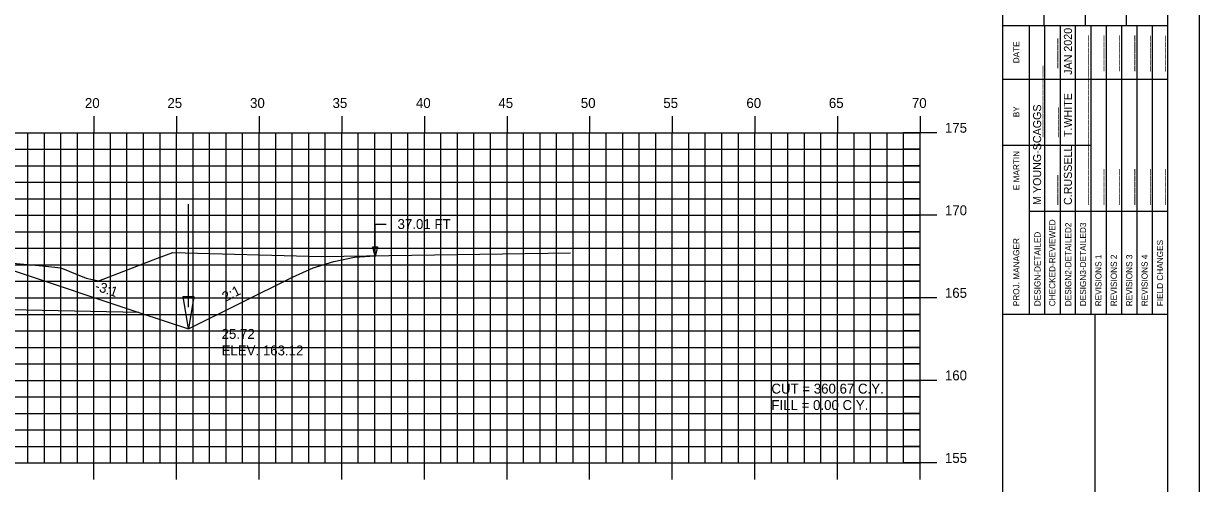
# Model space of a CAD drawing. Extents: x 1141646 to 1141816, y 608981 to 609091.
# Drawn here: x 1141744.8 to 1141815.9, y 609019.1 to 609047 of the extents above; entities that cross this region are included whole.
import ezdxf

# ---------------------------------------------------------------- set-up
doc = ezdxf.new("R2010")
doc.units = 0
for name, color, linetype in [('ANNOTATION', 7, 'Continuous'), ('BORDER', 7, 'Continuous'), ('D_Drainage_Ditch_Line', 7, 'Continuous'), ('D_Roadway_SlopeLines', 7, 'Continuous'), ('D_Roadway_SubGrade', 7, 'Continuous'), ('D_Text_Standard', 7, 'Continuous'), ('H_V ANNOTATION', 7, 'Continuous'), ('MAJOR', 7, 'Continuous'), ('MINOR', 7, 'Continuous'), ('PLOT BOUNDARY', 7, 'Continuous'), ('S_Roadway_Centerline', 7, 'Continuous')]:
    doc.layers.add(name, color=color, linetype=linetype)

msp = doc.modelspace()

# ---------------------------------------------------------------- linework, layer by layer
msp.add_lwpolyline([(1141690.206, 609033.804), (1141691.456, 609033.702), (1141692.706, 609033.45), (1141693.956, 609033.049), (1141695.206, 609032.498), (1141703.303, 609028.45), (1141706.303, 609029.45), (1141714.026, 609032.025), (1141714.027, 609032.025), (1141718.027, 609032.185), (1141729.027, 609032.405), (1141740.027, 609032.185), (1141744.027, 609032.025), (1141751.751, 609029.45), (1141754.751, 609028.45), (1141761.041, 609031.596), (1141762.291, 609032.145), (1141763.541, 609032.543), (1141764.791, 609032.789), (1141766.041, 609032.884)])
at = {"layer": 'BORDER'}
for p, q in [((1141804.027, 608984.335), (1141804.027, 609089.335)), ((1141806.527, 609046.838), (1141806.527, 609055.485)), ((1141809.027, 609046.838), (1141809.027, 609055.485)), ((1141811.527, 609046.838), (1141811.527, 609055.485)), ((1141804.027, 609046.838), (1141814.027, 609046.838)), ((1141804.027, 609029.338), (1141814.027, 609029.338)), ((1141809.618, 608994.338), (1141809.618, 609029.338))]:
    msp.add_line(p, q, dxfattribs=at)
msp.add_lwpolyline([(1141654.027, 608984.335), (1141814.027, 608984.335), (1141814.027, 609089.335), (1141654.027, 609089.335)], close=True, dxfattribs=at)
for points in [[(1141805.642, 609043.588), (1141805.642, 609046.838)], [(1141806.575, 609029.341), (1141806.575, 609046.838)], [(1141807.507, 609046.838), (1141807.507, 609029.341)], [(1141808.438, 609029.341), (1141808.438, 609046.838)], [(1141809.37, 609029.341), (1141809.37, 609046.838)], [(1141810.302, 609029.341), (1141810.302, 609046.838)], [(1141811.233, 609029.341), (1141811.233, 609046.838)], [(1141812.165, 609029.341), (1141812.165, 609046.838)], [(1141813.097, 609029.341), (1141813.097, 609046.838)], [(1141805.643, 609029.341), (1141805.643, 609046.132)], [(1141804.027, 609043.588), (1141814.027, 609043.588)], [(1141804.027, 609039.588), (1141805.643, 609039.588)], [(1141805.642, 609039.588), (1141809.369, 609039.588)], [(1141805.642, 609035.588), (1141814.027, 609035.588)]]:
    msp.add_lwpolyline(points, dxfattribs=at)
at = {"layer": 'D_Drainage_Ditch_Line'}
msp.add_line((1141754.751, 609029.763), (1141754.751, 609036.006), dxfattribs=at)
msp.add_lwpolyline([(1141754.423, 609030.419), (1141755.079, 609030.419), (1141754.751, 609028.45)], close=True, dxfattribs=at)
at = {"layer": 'D_Roadway_SlopeLines'}
for points in [[(1141754.751, 609028.45), (1141761.041, 609031.596), (1141762.291, 609032.145), (1141763.541, 609032.543), (1141764.791, 609032.789), (1141766.041, 609032.884)], [(1141751.751, 609029.45), (1141754.751, 609028.45)]]:
    msp.add_lwpolyline(points, dxfattribs=at)
at = {"layer": 'D_Roadway_SubGrade'}
msp.add_lwpolyline([(1141740.027, 609031.768), (1141740.027, 609031.935), (1141744.027, 609031.775), (1141744.027, 609032.025), (1141744.027, 609032.025), (1141751.751, 609029.45), (1141740.027, 609029.685)], close=True, dxfattribs=at)
at = {"layer": 'D_Text_Standard'}
msp.add_lwpolyline([(1141766.041, 609032.846), (1141766.042, 609034.804), (1141766.722, 609034.804)], dxfattribs=at)
msp.add_lwpolyline([(1141766.041, 609032.846), (1141765.896, 609033.428), (1141766.187, 609033.428)], close=True, dxfattribs=at)
at = {"layer": 'MAJOR'}
for p, q in [((1141749.027, 609041.337), (1141749.027, 609040.335)), ((1141754.027, 609041.337), (1141754.027, 609040.335)), ((1141759.027, 609041.337), (1141759.027, 609040.335)), ((1141764.027, 609041.337), (1141764.027, 609040.335)), ((1141769.027, 609041.337), (1141769.027, 609040.335)), ((1141774.027, 609041.337), (1141774.027, 609040.335)), ((1141779.027, 609041.337), (1141779.027, 609040.335)), ((1141784.027, 609041.337), (1141784.027, 609040.335)), ((1141789.027, 609041.337), (1141789.027, 609040.335)), ((1141794.027, 609041.337), (1141794.027, 609040.335)), ((1141799.027, 609041.337), (1141799.027, 609040.335)), ((1141659.027, 609040.335), (1141799.027, 609040.335)), ((1141659.027, 609040.335), (1141799.027, 609040.335)), ((1141749.027, 609020.335), (1141749.027, 609040.335)), ((1141754.027, 609020.335), (1141754.027, 609040.335)), ((1141759.027, 609020.335), (1141759.027, 609040.335)), ((1141764.027, 609020.335), (1141764.027, 609040.335)), ((1141769.027, 609020.335), (1141769.027, 609040.335)), ((1141774.027, 609020.335), (1141774.027, 609040.335)), ((1141779.027, 609020.335), (1141779.027, 609040.335)), ((1141784.027, 609020.335), (1141784.027, 609040.335)), ((1141789.027, 609020.335), (1141789.027, 609040.335)), ((1141794.027, 609020.335), (1141794.027, 609040.335)), ((1141800.029, 609040.335), (1141798.025, 609040.335)), ((1141799.027, 609020.335), (1141799.027, 609040.335)), ((1141799.027, 609020.335), (1141799.027, 609040.335)), ((1141659.027, 609035.335), (1141799.027, 609035.335)), ((1141800.029, 609035.335), (1141798.025, 609035.335)), ((1141659.027, 609030.335), (1141799.027, 609030.335)), ((1141800.029, 609030.335), (1141798.025, 609030.335)), ((1141659.027, 609025.335), (1141799.027, 609025.335)), ((1141800.029, 609025.335), (1141798.025, 609025.335)), ((1141659.027, 609020.335), (1141799.027, 609020.335)), ((1141659.027, 609020.335), (1141799.027, 609020.335)), ((1141749.027, 609019.333), (1141749.027, 609020.335)), ((1141754.027, 609019.333), (1141754.027, 609020.335)), ((1141759.027, 609019.333), (1141759.027, 609020.335)), ((1141764.027, 609019.333), (1141764.027, 609020.335)), ((1141769.027, 609019.333), (1141769.027, 609020.335)), ((1141774.027, 609019.333), (1141774.027, 609020.335)), ((1141779.027, 609019.333), (1141779.027, 609020.335)), ((1141784.027, 609019.333), (1141784.027, 609020.335)), ((1141789.027, 609019.333), (1141789.027, 609020.335)), ((1141794.027, 609019.333), (1141794.027, 609020.335)), ((1141800.029, 609020.335), (1141798.025, 609020.335)), ((1141799.027, 609019.333), (1141799.027, 609020.335))]:
    msp.add_line(p, q, dxfattribs=at)
at = {"layer": 'MINOR'}
for p, q in [((1141745.027, 609020.335), (1141745.027, 609040.335)), ((1141746.027, 609020.335), (1141746.027, 609040.335)), ((1141747.027, 609020.335), (1141747.027, 609040.335)), ((1141748.027, 609020.335), (1141748.027, 609040.335)), ((1141750.027, 609020.335), (1141750.027, 609040.335)), ((1141751.027, 609020.335), (1141751.027, 609040.335)), ((1141752.027, 609020.335), (1141752.027, 609040.335)), ((1141753.027, 609020.335), (1141753.027, 609040.335)), ((1141755.027, 609020.335), (1141755.027, 609040.335)), ((1141756.027, 609020.335), (1141756.027, 609040.335)), ((1141757.027, 609020.335), (1141757.027, 609040.335)), ((1141758.027, 609020.335), (1141758.027, 609040.335)), ((1141760.027, 609020.335), (1141760.027, 609040.335)), ((1141761.027, 609020.335), (1141761.027, 609040.335)), ((1141762.027, 609020.335), (1141762.027, 609040.335)), ((1141763.027, 609020.335), (1141763.027, 609040.335)), ((1141765.027, 609020.335), (1141765.027, 609040.335)), ((1141766.027, 609020.335), (1141766.027, 609040.335)), ((1141767.027, 609020.335), (1141767.027, 609040.335)), ((1141768.027, 609020.335), (1141768.027, 609040.335)), ((1141770.027, 609020.335), (1141770.027, 609040.335)), ((1141771.027, 609020.335), (1141771.027, 609040.335)), ((1141772.027, 609020.335), (1141772.027, 609040.335)), ((1141773.027, 609020.335), (1141773.027, 609040.335)), ((1141775.027, 609020.335), (1141775.027, 609040.335)), ((1141776.027, 609020.335), (1141776.027, 609040.335)), ((1141777.027, 609020.335), (1141777.027, 609040.335)), ((1141778.027, 609020.335), (1141778.027, 609040.335)), ((1141780.027, 609020.335), (1141780.027, 609040.335)), ((1141781.027, 609020.335), (1141781.027, 609040.335)), ((1141782.027, 609020.335), (1141782.027, 609040.335)), ((1141783.027, 609020.335), (1141783.027, 609040.335)), ((1141785.027, 609020.335), (1141785.027, 609040.335)), ((1141786.027, 609020.335), (1141786.027, 609040.335)), ((1141787.027, 609020.335), (1141787.027, 609040.335)), ((1141788.027, 609020.335), (1141788.027, 609040.335)), ((1141790.027, 609020.335), (1141790.027, 609040.335)), ((1141791.027, 609020.335), (1141791.027, 609040.335)), ((1141792.027, 609020.335), (1141792.027, 609040.335)), ((1141793.027, 609020.335), (1141793.027, 609040.335)), ((1141795.027, 609020.335), (1141795.027, 609040.335)), ((1141796.027, 609020.335), (1141796.027, 609040.335)), ((1141797.027, 609020.335), (1141797.027, 609040.335)), ((1141798.027, 609020.335), (1141798.027, 609040.335)), ((1141659.027, 609039.335), (1141799.027, 609039.335)), ((1141799.027, 609039.335), (1141798.025, 609039.335)), ((1141659.027, 609038.335), (1141799.027, 609038.335)), ((1141799.027, 609038.335), (1141798.025, 609038.335)), ((1141659.027, 609037.335), (1141799.027, 609037.335)), ((1141799.027, 609037.335), (1141798.025, 609037.335)), ((1141659.027, 609036.335), (1141799.027, 609036.335)), ((1141799.027, 609036.335), (1141798.025, 609036.335)), ((1141659.027, 609034.335), (1141799.027, 609034.335)), ((1141799.027, 609034.335), (1141798.025, 609034.335)), ((1141659.027, 609033.335), (1141799.027, 609033.335)), ((1141799.027, 609033.335), (1141798.025, 609033.335)), ((1141659.027, 609032.335), (1141799.027, 609032.335)), ((1141799.027, 609032.335), (1141798.025, 609032.335)), ((1141659.027, 609031.335), (1141799.027, 609031.335)), ((1141799.027, 609031.335), (1141798.025, 609031.335)), ((1141659.027, 609029.335), (1141799.027, 609029.335)), ((1141799.027, 609029.335), (1141798.025, 609029.335)), ((1141659.027, 609028.335), (1141799.027, 609028.335)), ((1141799.027, 609028.335), (1141798.025, 609028.335)), ((1141659.027, 609027.335), (1141799.027, 609027.335)), ((1141799.027, 609027.335), (1141798.025, 609027.335)), ((1141659.027, 609026.335), (1141799.027, 609026.335)), ((1141799.027, 609026.335), (1141798.025, 609026.335)), ((1141659.027, 609024.335), (1141799.027, 609024.335)), ((1141799.027, 609024.335), (1141798.025, 609024.335)), ((1141659.027, 609023.335), (1141799.027, 609023.335)), ((1141799.027, 609023.335), (1141798.025, 609023.335)), ((1141659.027, 609022.335), (1141799.027, 609022.335)), ((1141799.027, 609022.335), (1141798.025, 609022.335)), ((1141659.027, 609021.335), (1141799.027, 609021.335)), ((1141799.027, 609021.335), (1141798.025, 609021.335))]:
    msp.add_line(p, q, dxfattribs=at)
at = {"layer": 'PLOT BOUNDARY'}
msp.add_lwpolyline([(1141645.934, 608981.276), (1141815.934, 608981.276), (1141815.934, 609091.276), (1141645.934, 609091.276)], close=True, dxfattribs=at)
at = {"layer": 'S_Roadway_Centerline'}
msp.add_lwpolyline([(1141678.167, 609033.767), (1141679.234, 609034.048), (1141698.041, 609033.63), (1141705.97, 609033.574), (1141711.406, 609031.629), (1141712.938, 609031.34), (1141715.436, 609031.97), (1141716.134, 609032.093), (1141717.099, 609032.186), (1141720.325, 609032.555), (1141723.008, 609032.647), (1141731.533, 609032.829), (1141740.258, 609032.604), (1141742.967, 609032.542), (1141745.916, 609032.271), (1141747.023, 609032.157), (1141748.557, 609031.535), (1141749.326, 609031.358), (1141752.88, 609032.733), (1141753.796, 609033.073), (1141762.777, 609032.834), (1141777.873, 609033.068)], dxfattribs=at)

# ---------------------------------------------------------------- texts
at = {"layer": 'ANNOTATION'}
for s, rotation, p in [('-3:1', 341.56521, (1141749.039, 609030.809)), ('2:1', 26.56505, (1141756.969, 609030.077))]:
    msp.add_text(s, height=0.6, rotation=rotation, dxfattribs=at).set_placement(p)
at = {"layer": 'BORDER'}
for s, height, p in [('JAN 2020', 0.4845, (1141808.214, 609043.843)), ('DATE', 0.3714, (1141805.032, 609044.544)), ('_____', 0.4845, (1141807.245, 609044.243)), ('______', 0.4845, (1141809.108, 609044.063)), ('______', 0.4845, (1141810.04, 609044.065)), ('______', 0.4845, (1141810.972, 609044.067)), ('______', 0.4845, (1141811.903, 609044.067)), ('______', 0.4845, (1141812.835, 609044.036)), ('______', 0.4845, (1141813.767, 609044.036)), ('____________', 0.48455, (1141806.35, 609040.073)), ('____________', 0.48455, (1141809.108, 609040.073)), ('T.WHITE', 0.4845, (1141808.214, 609040.073)), ('M YOUNG-SCAGGS', 0.48455, (1141806.35, 609035.961)), ('BY', 0.3714, (1141805.032, 609041.273)), ('_____', 0.4845, (1141807.282, 609040.073)), ('____________', 0.48455, (1141809.108, 609035.961)), ('E MARTIN', 0.3727, (1141805.032, 609036.855)), ('C.RUSSELL', 0.4845, (1141808.214, 609035.961)), ('_____', 0.4845, (1141807.245, 609035.961)), ('______', 0.4845, (1141810.04, 609035.961)), ('______', 0.4845, (1141810.972, 609035.961)), ('______', 0.4845, (1141811.903, 609035.961)), ('______', 0.4845, (1141812.835, 609035.961)), ('______', 0.4845, (1141813.767, 609035.961)), ('CHECKED-REVIEWED', 0.37275, (1141807.208, 609029.826)), ('DESIGN3-DETAILED3', 0.37275, (1141809.072, 609029.826)), ('DESIGN-DETAILED', 0.37275, (1141806.314, 609029.826)), ('DESIGN2-DETAILED2', 0.37275, (1141808.177, 609029.826)), ('PROJ. MANAGER', 0.37275, (1141805.032, 609029.826)), ('FIELD CHANGES', 0.37275, (1141813.73, 609029.826)), ('REVISIONS 1', 0.37275, (1141810.003, 609029.826)), ('REVISIONS 2', 0.37275, (1141810.935, 609029.826)), ('REVISIONS 3', 0.37275, (1141811.867, 609029.826)), ('REVISIONS 4', 0.37275, (1141812.799, 609029.826))]:
    msp.add_text(s, height=height, rotation=90, dxfattribs=at).set_placement(p)
at = {"layer": 'D_Text_Standard'}
for s, p in [('37.01 FT', (1141767.402, 609034.504)), ('25.72', (1141756.751, 609027.85)), ('ELEV. 163.12', (1141756.751, 609026.848)), ('CUT = 360.67 C.Y.', (1141790.027, 609024.535)), ('FILL = 0.00 C.Y.', (1141790.027, 609023.539))]:
    msp.add_text(s, height=0.6, dxfattribs=at).set_placement(p)
at = {"layer": 'H_V ANNOTATION'}
for s, p in [('20', (1141748.481, 609041.835)), ('25', (1141753.473, 609041.835)), ('30', (1141758.476, 609041.835)), ('35', (1141763.468, 609041.835)), ('40', (1141768.513, 609041.835)), ('45', (1141773.505, 609041.835)), ('50', (1141778.492, 609041.835)), ('55', (1141783.484, 609041.835)), ('60', (1141788.513, 609041.835)), ('65', (1141793.505, 609041.835)), ('70', (1141798.529, 609041.835)), ('175', (1141800.527, 609040.335)), ('170', (1141800.527, 609035.335)), ('165', (1141800.527, 609030.335)), ('160', (1141800.527, 609025.335)), ('155', (1141800.527, 609020.335))]:
    msp.add_text(s, height=0.6, dxfattribs=at).set_placement(p)

doc.saveas('drawing.dxf')
